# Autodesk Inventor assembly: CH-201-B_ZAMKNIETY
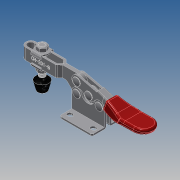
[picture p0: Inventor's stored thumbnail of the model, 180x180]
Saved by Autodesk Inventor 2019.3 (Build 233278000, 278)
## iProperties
Company: Î¢ÈíÖÐ¹ú
Created: 2012-01
Part Number: CH-201-B_ZAMKNIETY
Material: Ogólny
Description: STEP AP203
Document SubType Name: Assembly
Designer: CADENGINEERING4
Sending System: SolidWorks 2010
Preprocessor: SwSTEP 2.0
Title: CH-201-B.STEP
Author: Î¢ÈíÓÃ»§
Revision Number: ÈÎºÎ
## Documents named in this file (9)
- E:\STRONA\Horizontal toggle clamp\CH-201-B\CH-201-B_ZAMKNIETY.iam
- E:\STRONA\Horizontal toggle clamp\CH-201-B\201-B-04.ipt
- E:\STRONA\Horizontal toggle clamp\CH-201-B\201-B-06.ipt
- E:\STRONA\Horizontal toggle clamp\CH-201-B\14134-02.ipt
- E:\STRONA\Horizontal toggle clamp\CH-201-B\201-B-01.ipt
- E:\STRONA\Horizontal toggle clamp\CH-201-B\14134.ipt
- E:\STRONA\Horizontal toggle clamp\CH-201-B\FW140.ipt
- E:\STRONA\Horizontal toggle clamp\CH-201-B\201-B-02.ipt
- E:\STRONA\Horizontal toggle clamp\CH-201-B\201-B.iam
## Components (14 placed, 14 different names)
1. 201-B-04_1 — Zestawiające:14, Zestawiające:15, Zestawiające:16, Zestawiające:22
2. 201-B-06_2 — Zestawiające:10, Zestawiające:11, Zestawiające:27
3. 14134-02_3 — Równoległe:3, Zestawiające:2, Zestawiające:7
4. 201-B-04_4 — Zestawiające:14, Zestawiające:15, Zestawiające:16, Zestawiające:17, Zestawiające:18, Zestawiające:21
5. 201-B-01_5 — Zestawiające:17, Zestawiające:18, Zestawiające:19, Zestawiające:20, Zestawiające:23, Zestawiające:24, Zestawiające:26, Przejściowe:1
6. 14134_6 — Równoległe:3, Zestawiające:1, Zestawiające:2, Zestawiające:3, Zestawiające:4, Zestawiające:9
7. FW140_7 — Równoległe:2, Zestawiające:4, Zestawiające:5, Zestawiające:6
8. 14134-02_8 — Zestawiające:1, Zestawiające:5
9. 201-B-02_9 — Równoległe:1, Zestawiające:6, Zestawiające:8, Zestawiające:9, Zestawiające:25, Zestawiające:26, Zestawiające:27
10. FW140_10 — Równoległe:1, Równoległe:2, Zestawiające:3, Zestawiające:7, Zestawiające:8
11. 201-B_11 [sub-assembly] — Zestawiające:10, Zestawiające:11, Zestawiające:12, Zestawiające:13, Zestawiające:22, Przejściowe:1
12. 201-B-06_12 — Zestawiające:19, Zestawiające:20
13. 201-B-06_13 — Zestawiające:12, Zestawiające:13, Zestawiające:21
14. 201-B-06_14 — Zestawiające:23, Zestawiające:24, Zestawiające:25
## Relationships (31: Mate 27, Flush 3, Transitional 1)
- Równoległe:1 [Flush]: 201-B-02_9 ↔ FW140_10
- Równoległe:2 [Flush]: FW140_7 ↔ FW140_10
- Równoległe:3 [Flush]: 14134-02_3 ↔ 14134_6
- Zestawiające:1 [Mate]: 14134_6 ↔ 14134-02_8
- Zestawiające:2 [Mate]: 14134-02_3 ↔ 14134_6
- Zestawiające:3 [Mate]: 14134_6 ↔ FW140_10
- Zestawiające:4 [Mate]: 14134_6 ↔ FW140_7
- Zestawiające:5 [Mate]: FW140_7 ↔ 14134-02_8
- Zestawiające:6 [Mate]: FW140_7 ↔ 201-B-02_9
- Zestawiające:7 [Mate]: 14134-02_3 ↔ FW140_10
- Zestawiające:8 [Mate]: 201-B-02_9 ↔ FW140_10
- Zestawiające:9 [Mate]: 14134_6 ↔ 201-B-02_9
- Zestawiające:10 [Mate]: 201-B-06_2 ↔ 201-B_11
- Zestawiające:11 [Mate]: 201-B-06_2 ↔ 201-B_11
- Zestawiające:12 [Mate]: 201-B_11 ↔ 201-B-06_13
- Zestawiające:13 [Mate]: 201-B_11 ↔ 201-B-06_13
- Zestawiające:14 [Mate]: 201-B-04_1 ↔ 201-B-04_4
- Zestawiające:15 [Mate]: 201-B-04_1 ↔ 201-B-04_4
- Zestawiające:16 [Mate]: 201-B-04_1 ↔ 201-B-04_4
- Zestawiające:17 [Mate]: 201-B-04_4 ↔ 201-B-01_5
- Zestawiające:18 [Mate]: 201-B-04_4 ↔ 201-B-01_5
- Zestawiające:19 [Mate]: 201-B-01_5 ↔ 201-B-06_12
- Zestawiające:20 [Mate]: 201-B-01_5 ↔ 201-B-06_12
- Zestawiające:21 [Mate]: 201-B-04_4 ↔ 201-B-06_13
- Zestawiające:22 [Mate]: 201-B-04_1 ↔ 201-B_11
- Zestawiające:23 [Mate]: 201-B-01_5 ↔ 201-B-06_14
- Zestawiające:24 [Mate]: 201-B-01_5 ↔ 201-B-06_14
- Zestawiające:25 [Mate]: 201-B-02_9 ↔ 201-B-06_14
- Zestawiające:26 [Mate]: 201-B-01_5 ↔ 201-B-02_9
- Zestawiające:27 [Mate]: 201-B-06_2 ↔ 201-B-02_9
- Przejściowe:1 [Transitional]: 201-B-01_5 ↔ 201-B_11
